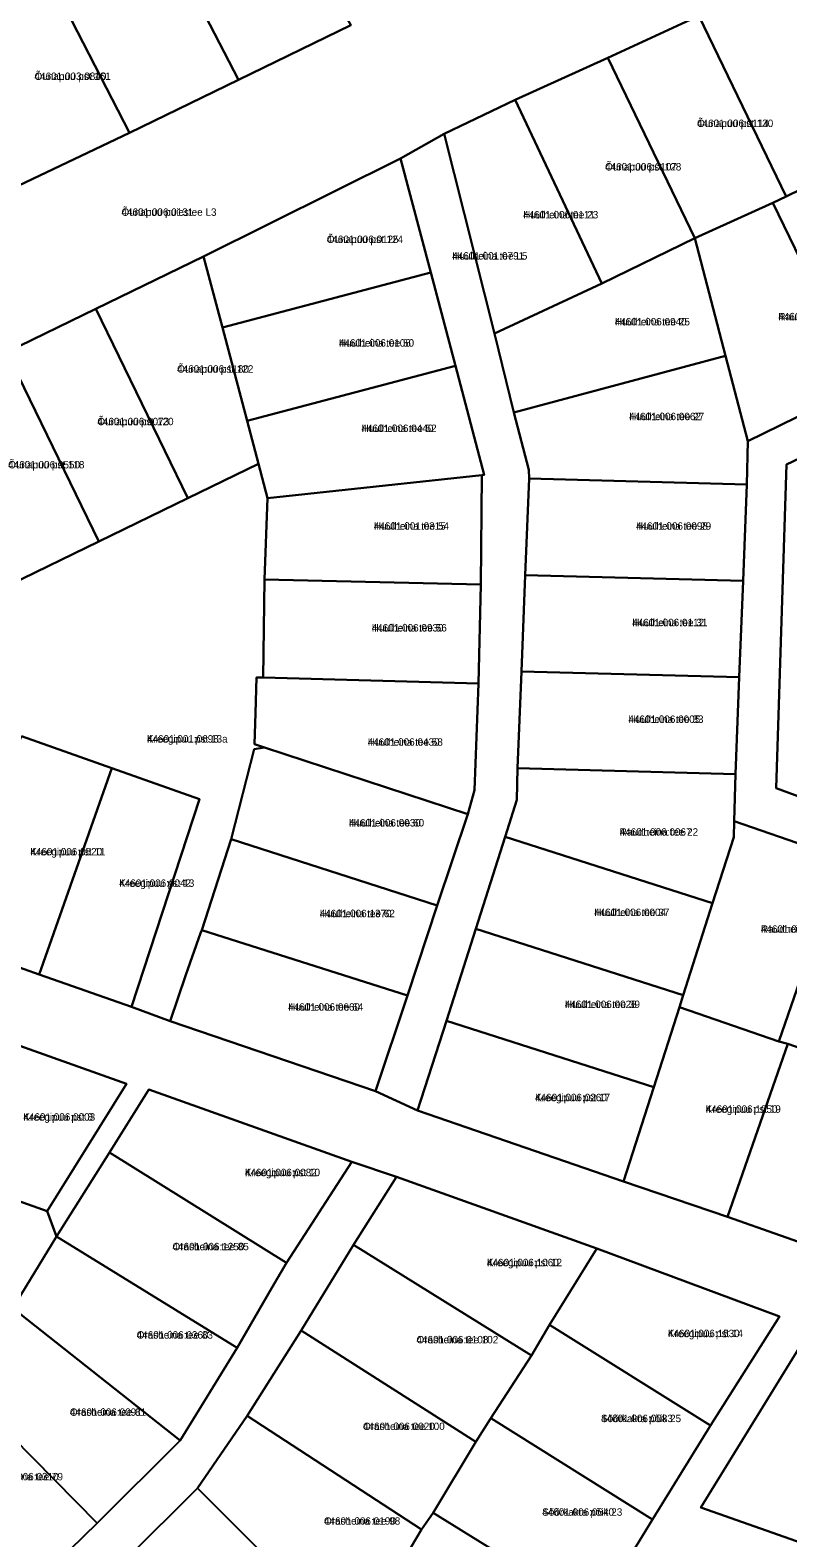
# Model space of a CAD drawing. Extents: x 551843 to 558501, y 6589003 to 6595718.
# Drawn here: x 553719.3 to 553872.3, y 6593051.3 to 6593355.7 of the extents above; entities that cross this region are included whole.
import ezdxf

# ---------------------------------------------------------------- set-up
doc = ezdxf.new("R2010")
doc.units = 0
for name, color, linetype in [('L_AADRESS', 7, 'Continuous'), ('PIIR', 7, 'Continuous'), ('TUNNUS', 7, 'Continuous')]:
    doc.layers.add(name, color=color, linetype=linetype)

msp = doc.modelspace()

# ---------------------------------------------------------------- linework, layer by layer
at = {"layer": 'PIIR'}
for points in [[(553755.85, 6593382.8), (553766.18, 6593387.81), (553784.07, 6593356.73), (553761.39, 6593345.7), (553744.97, 6593377.51)], [(553739.43, 6593335.04), (553723.03, 6593366.85), (553744.97, 6593377.51), (553761.39, 6593345.7)], [(553701.02, 6593356.45), (553717.5, 6593364.16), (553723.03, 6593366.85), (553739.43, 6593335.04), (553717.06, 6593324.38)], [(553854.3, 6593358.62), (553872.59, 6593367.51), (553890.23, 6593331.05), (553887.78, 6593329.87), (553871.99, 6593322.18)], [(553835.93, 6593350.16), (553854.3, 6593358.62), (553871.99, 6593322.18), (553869.25, 6593320.86), (553853.55, 6593313.74)], [(553817.25, 6593341.68), (553835.93, 6593350.16), (553853.55, 6593313.74), (553834.77, 6593304.59)], [(553802.94, 6593334.83), (553817.25, 6593341.68), (553834.77, 6593304.59), (553813.05, 6593294.48)], [(553810.52, 6593265.91), (553810.99, 6593265.94), (553805.21, 6593287.98), (553800.2, 6593306.84), (553794.13, 6593329.84), (553802.94, 6593334.83), (553813.05, 6593294.48), (553816.98, 6593278.53), (553820.03, 6593266.97), (553820.05, 6593265.2), (553819.28, 6593245.73), (553818.51, 6593226.23), (553817.74, 6593206.75), (553817.56, 6593200.35), (553815.24, 6593192.88), (553809.3, 6593174.31), (553803.37, 6593155.74), (553797.56, 6593137.62), (553789.06, 6593141.51), (553795.53, 6593160.86), (553801.53, 6593178.99), (553807.71, 6593197.46), (553809.04, 6593202.27), (553809.82, 6593223.82), (553810.32, 6593243.85)], [(553758.16, 6593295.7), (553754.37, 6593310.06), (553794.13, 6593329.84), (553800.2, 6593306.84)], [(553887.78, 6593329.87), (553905.73, 6593292.98), (553887.19, 6593283.97), (553869.25, 6593320.86), (553871.99, 6593322.18)], [(553869.25, 6593320.86), (553887.19, 6593283.97), (553864.2, 6593272.79), (553859.74, 6593289.98), (553853.55, 6593313.74)], [(553834.77, 6593304.59), (553853.55, 6593313.74), (553859.74, 6593289.98), (553816.98, 6593278.53), (553813.05, 6593294.48)], [(553732.62, 6593299.48), (553754.37, 6593310.06), (553758.16, 6593295.7), (553763.16, 6593276.85), (553765.42, 6593268.17), (553751.19, 6593261.25)], [(553758.16, 6593295.7), (553800.2, 6593306.84), (553805.21, 6593287.98), (553763.16, 6593276.85)], [(553714.63, 6593290.73), (553732.62, 6593299.48), (553751.19, 6593261.25), (553733.19, 6593252.5)], [(553696.64, 6593281.99), (553714.63, 6593290.73), (553733.19, 6593252.5), (553715.21, 6593243.76)], [(553859.74, 6593289.98), (553864.2, 6593272.79), (553864, 6593264.02), (553820.05, 6593265.2), (553820.03, 6593266.97), (553816.98, 6593278.53)], [(553765.42, 6593268.17), (553763.16, 6593276.85), (553805.21, 6593287.98), (553810.99, 6593265.94), (553810.52, 6593265.91), (553767.26, 6593261.24)], [(553898.78, 6593280.77), (553919.51, 6593228.18), (553925.34, 6593182.28), (553869.91, 6593202.68), (553872.03, 6593268.08)], [(553872.03, 6593268.08), (553869.91, 6593202.68), (553925.34, 6593182.28), (553919.51, 6593228.18), (553898.78, 6593280.77)], [(553810.32, 6593243.85), (553766.67, 6593244.84), (553767.26, 6593261.24), (553810.52, 6593265.91)], [(553819.28, 6593245.73), (553820.05, 6593265.2), (553864, 6593264.02), (553863.26, 6593244.57)], [(553766.67, 6593244.84), (553810.32, 6593243.85), (553809.82, 6593223.82), (553766.35, 6593225.03)], [(553819.28, 6593245.73), (553863.26, 6593244.57), (553862.49, 6593225.08), (553818.51, 6593226.23)], [(553765.01, 6593225.07), (553766.35, 6593225.03), (553809.82, 6593223.82), (553809.04, 6593202.27), (553807.71, 6593197.46), (553766.66, 6593210.92), (553764.66, 6593211.58), (553764.83, 6593217.86)], [(553818.51, 6593226.23), (553862.49, 6593225.08), (553861.72, 6593205.52), (553817.74, 6593206.75)], [(553717.61, 6593213.17), (553735.8, 6593206.72), (553721.14, 6593165.08), (553702.95, 6593171.53)], [(553801.53, 6593178.99), (553759.9, 6593192.43), (553764.54, 6593210.58), (553766.66, 6593210.92), (553807.71, 6593197.46)], [(553735.8, 6593206.72), (553753.5, 6593200.49), (553739.77, 6593158.52), (553721.14, 6593165.08)], [(553817.56, 6593200.35), (553817.74, 6593206.75), (553861.72, 6593205.52), (553861.46, 6593196.05), (553861.39, 6593192.79), (553857.12, 6593179.46), (553815.24, 6593192.88)], [(553851.18, 6593160.89), (553857.12, 6593179.46), (553861.39, 6593192.79), (553861.46, 6593196.05), (553883.28, 6593188.51), (553870.51, 6593151.58), (553850.43, 6593158.51)], [(553801.53, 6593178.99), (553795.53, 6593160.86), (553754, 6593174.03), (553759.9, 6593192.43)], [(553815.24, 6593192.88), (553857.12, 6593179.46), (553851.18, 6593160.89), (553809.3, 6593174.31)], [(553903.79, 6593181.43), (553890.99, 6593144.48), (553872.28, 6593151.07), (553870.51, 6593151.58), (553883.28, 6593188.51)], [(553789.06, 6593141.51), (553747.64, 6593155.65), (553750.76, 6593164.99), (553753.71, 6593173.45), (553754, 6593174.03), (553795.53, 6593160.86)], [(553851.18, 6593160.89), (553850.43, 6593158.51), (553845.25, 6593142.31), (553803.37, 6593155.74), (553809.3, 6593174.31)], [(553870.51, 6593151.58), (553872.28, 6593151.07), (553860.1, 6593116.14), (553839.15, 6593123.26), (553845.25, 6593142.31), (553850.43, 6593158.51)], [(553845.25, 6593142.31), (553839.15, 6593123.26), (553797.56, 6593137.62), (553803.37, 6593155.74)], [(553708.29, 6593153.86), (553738.79, 6593143.01), (553722.79, 6593117.28), (553698.37, 6593125.97)], [(553890.99, 6593144.48), (553893.7, 6593143.53), (553881.51, 6593108.6), (553860.1, 6593116.14), (553872.28, 6593151.07)], [(553735.35, 6593129.11), (553743.32, 6593141.86), (553784.29, 6593127.26), (553771.12, 6593106.86)], [(553667.82, 6593136.86), (553698.37, 6593125.97), (553722.79, 6593117.28), (553724.65, 6593112.16), (553715.84, 6593097.69), (553702.72, 6593084.85), (553688.9, 6593070.71), (553676.07, 6593057.76), (553659.09, 6593047.13), (553642.16, 6593036.49), (553629.16, 6593028.32), (553627.05, 6593033.11), (553664.19, 6593056.27), (553658.97, 6593070.69), (553652.27, 6593089.53), (553647.12, 6593103.99), (553648.53, 6593107.89), (553659.67, 6593124.55)], [(553643.89, 6592987.38), (553664.77, 6593000.5), (553681.43, 6593011.49), (553702.17, 6593024.66), (553719.27, 6593041.04), (553732.87, 6593054.27), (553749.62, 6593070.96), (553761.14, 6593089.7), (553768.13, 6593101.84), (553771.12, 6593106.86), (553784.29, 6593127.26), (553793.28, 6593124.2), (553784.6, 6593110.51), (553774.04, 6593093.19), (553763.13, 6593075.95), (553753.11, 6593061.38), (553738.72, 6593047.04), (553724.11, 6593032.4), (553709.85, 6593018.28), (553708.91, 6593017.72), (553696.33, 6593009.65), (553678.47, 6592998.33), (553659.91, 6592986.98), (553646.3, 6592978.3)], [(553724.65, 6593112.16), (553735.35, 6593129.11), (553771.12, 6593106.86), (553768.13, 6593101.84), (553761.14, 6593089.7)], [(553784.6, 6593110.51), (553793.28, 6593124.2), (553833.75, 6593109.74), (553824.18, 6593094.37), (553820.54, 6593088.16)], [(553715.84, 6593097.69), (553724.65, 6593112.16), (553761.14, 6593089.7), (553749.62, 6593070.96)], [(553784.6, 6593110.51), (553820.54, 6593088.16), (553812.37, 6593075.48), (553809.31, 6593070.71), (553774.04, 6593093.19)], [(553833.75, 6593109.74), (553870.59, 6593096.02), (553856.67, 6593073.99), (553824.18, 6593094.37)], [(553702.72, 6593084.85), (553715.84, 6593097.69), (553749.62, 6593070.96), (553732.87, 6593054.27)], [(553844.97, 6593055.03), (553812.37, 6593075.48), (553820.54, 6593088.16), (553824.18, 6593094.37), (553856.67, 6593073.99)], [(553854.75, 6593057.46), (553877.3, 6593094.1), (553895.01, 6593087.85), (553875.19, 6593050.25)], [(553763.13, 6593075.95), (553774.04, 6593093.19), (553809.31, 6593070.71), (553800.73, 6593056.39), (553798.33, 6593053.01)], [(553719.27, 6593041.04), (553688.9, 6593070.71), (553702.72, 6593084.85), (553732.87, 6593054.27)], [(553798.33, 6593053.01), (553789.9, 6593038.83), (553782.47, 6593032.03), (553753.11, 6593061.38), (553763.13, 6593075.95)], [(553800.73, 6593056.39), (553809.31, 6593070.71), (553812.37, 6593075.48), (553844.97, 6593055.03), (553833.4, 6593036.12)], [(553753.11, 6593061.38), (553782.47, 6593032.03), (553775.73, 6593024.7), (553768.31, 6593017.24), (553738.72, 6593047.04)], [(553789.9, 6593038.83), (553798.33, 6593053.01), (553800.73, 6593056.39), (553833.4, 6593036.12), (553820.22, 6593014.77)]]:
    msp.add_lwpolyline(points, close=True, dxfattribs=at)
for points in [[(553854.3, 6593358.62), (553835.93, 6593350.16), (553817.25, 6593341.68), (553802.94, 6593334.83), (553794.13, 6593329.84), (553754.37, 6593310.06), (553732.62, 6593299.48), (553714.63, 6593290.73)], [(553717.06, 6593324.38), (553739.43, 6593335.04), (553761.39, 6593345.7), (553784.07, 6593356.73)], [(553883.28, 6593188.51), (553861.46, 6593196.05), (553861.72, 6593205.52), (553862.49, 6593225.08), (553863.26, 6593244.57), (553864, 6593264.02), (553864.2, 6593272.79), (553887.19, 6593283.97)], [(553715.21, 6593243.76), (553733.19, 6593252.5), (553751.19, 6593261.25), (553765.42, 6593268.17), (553767.26, 6593261.24), (553766.67, 6593244.84), (553766.35, 6593225.03), (553765.01, 6593225.07), (553764.83, 6593217.86), (553764.66, 6593211.58), (553766.66, 6593210.92), (553764.54, 6593210.58), (553759.9, 6593192.43), (553754, 6593174.03), (553753.71, 6593173.45), (553750.76, 6593164.99), (553747.64, 6593155.65), (553739.77, 6593158.52), (553753.5, 6593200.49), (553735.8, 6593206.72), (553717.61, 6593213.17)], [(553702.95, 6593171.53), (553721.14, 6593165.08), (553739.77, 6593158.52), (553747.64, 6593155.65), (553789.06, 6593141.51), (553797.56, 6593137.62), (553839.15, 6593123.26), (553860.1, 6593116.14), (553881.51, 6593108.6), (553902.87, 6593101.36), (553924.28, 6593093.82), (553939.21, 6593088.15), (553965.62, 6593118.07), (553974.77, 6593128.95), (553993.24, 6593150.17), (554007.57, 6593145.12), (553973.99, 6593106.07), (553971.14, 6593106.63), (553953.7, 6593085.37), (553988.53, 6593074.47), (553988.44, 6593074.16), (554031.74, 6593060.29), (554035.59, 6593039.14)], [(553833.4, 6593036.12), (553844.97, 6593055.03), (553856.67, 6593073.99), (553870.59, 6593096.02), (553833.75, 6593109.74), (553793.28, 6593124.2), (553784.29, 6593127.26), (553743.32, 6593141.86), (553735.35, 6593129.11), (553724.65, 6593112.16), (553722.79, 6593117.28), (553738.79, 6593143.01), (553708.29, 6593153.86)], [(554031.39, 6593040.61), (553988.97, 6593055.28), (553958.82, 6593066), (553932.68, 6593074.58), (553913.88, 6593081.12), (553895.01, 6593087.85), (553877.3, 6593094.1), (553854.75, 6593057.46), (553875.19, 6593050.25)]]:
    msp.add_lwpolyline(points, dxfattribs=at)

# ---------------------------------------------------------------- texts
at = {"layer": 'L_AADRESS'}
for s, p in [('Õunapuu pst 161', (553720.23, 6593345.69)), ('Õunapuu pst 130', (553853.96, 6593336.19)), ('Õunapuu pst 128', (553835.4, 6593327.41)), ('Õunapuu puiestee L3', (553737.78, 6593318.26)), ('Huulheina tee 23', (553818.86, 6593317.73)), ('Õunapuu pst 124', (553779.23, 6593312.77)), ('Huulheina tee L5', (553804.55, 6593309.42)), ('Raudheina tee 12', (553870.37, 6593297.17)), ('Huulheina tee 25', (553837.37, 6593296.13)), ('Huulheina tee 50', (553781.68, 6593291.85)), ('Õunapuu pst 122', (553749.02, 6593286.59)), ('Õunapuu pst 120', (553732.91, 6593275.98)), ('Huulheina tee 27', (553840.25, 6593277)), ('Huulheina tee 52', (553786.23, 6593274.61)), ('Õunapuu pst 118', (553714.91, 6593267.26)), ('Huulheina tee 54', (553788.73, 6593254.88)), ('Huulheina tee 29', (553841.65, 6593254.88)), ('Huulheina tee 31', (553840.89, 6593235.4)), ('Huulheina tee 56', (553788.29, 6593234.33)), ('Huulheina tee 33', (553840.11, 6593215.88)), ('Kreegipuu pst 13a', (553742.92, 6593211.91)), ('Huulheina tee 58', (553787.49, 6593211.27)), ('Huulheina tee 60', (553783.71, 6593194.96)), ('Raudheina tee 22', (553838.35, 6593193.11)), ('Kreegipuu pst 11', (553719.38, 6593189.12)), ('Kreegipuu pst 13', (553737.32, 6593182.78)), ('Huulheina tee 62', (553777.8, 6593176.65)), ('Huulheina tee 37', (553833.21, 6593176.88)), ('Raudheina tee 24', (553866.86, 6593173.51)), ('Huulheina tee 64', (553771.42, 6593157.77)), ('Huulheina tee 39', (553827.28, 6593158.31)), ('Kreegipuu pst 17', (553821.26, 6593139.5)), ('Kreegipuu pst 8', (553717.97, 6593135.57)), ('Kreegipuu pst 19', (553855.71, 6593137.16)), ('Kreegipuu pst 10', (553762.7, 6593124.36)), ('Orasheina tee 85', (553748.08, 6593109.4)), ('Kreegipuu pst 12', (553811.55, 6593106.18)), ('Orasheina tee 83', (553740.85, 6593091.56)), ('Orasheina tee 102', (553797.34, 6593090.61)), ('Kreegipuu pst 14', (553848.07, 6593091.86)), ('Orasheina tee 81', (553727.37, 6593075.98)), ('Sõõrkakra põik 25', (553834.58, 6593074.7)), ('Orasheina tee 100', (553786.53, 6593073.1)), ('Orasheina tee 79', (553710.58, 6593062.95)), ('Sõõrkakra põik 23', (553822.71, 6593055.8)), ('Orasheina tee 98', (553778.66, 6593053.99))]:
    msp.add_text(s, height=1.5, dxfattribs=at).set_placement(p)
at = {"layer": 'TUNNUS'}
for s, p in [('44601:003:0840', (553720.23, 6593345.69)), ('44601:006:0114', (553853.96, 6593336.19)), ('44601:006:0107', (553835.4, 6593327.41)), ('44601:006:0131', (553737.78, 6593318.26)), ('44601:006:0111', (553818.86, 6593317.73)), ('44601:006:0125', (553779.23, 6593312.77)), ('44601:001:0791', (553804.55, 6593309.42)), ('44601:006:0990', (553870.37, 6593297.17)), ('44601:006:0940', (553837.37, 6593296.13)), ('44601:006:0106', (553781.68, 6593291.85)), ('44601:006:1180', (553749.02, 6593286.59)), ('44601:006:0073', (553732.91, 6593275.98)), ('44601:006:0062', (553840.25, 6593277)), ('44601:006:0440', (553786.23, 6593274.61)), ('44601:006:0550', (553714.91, 6593267.26)), ('44601:001:0315', (553788.73, 6593254.88)), ('44601:006:0098', (553841.65, 6593254.88)), ('44601:006:0112', (553840.89, 6593235.4)), ('44601:006:0930', (553788.29, 6593234.33)), ('44601:006:0005', (553840.11, 6593215.88)), ('44601:001:0698', (553742.92, 6593211.91)), ('44601:006:0430', (553787.49, 6593211.27)), ('44601:006:0030', (553783.71, 6593194.96)), ('44601:006:0067', (553838.35, 6593193.11)), ('44601:006:0520', (553719.38, 6593189.12)), ('44601:006:0042', (553737.32, 6593182.78)), ('44601:006:1370', (553777.8, 6593176.65)), ('44601:006:0004', (553833.21, 6593176.88)), ('44601:006:0008', (553866.86, 6593173.51)), ('44601:006:0660', (553771.42, 6593157.77)), ('44601:006:0028', (553827.28, 6593158.31)), ('44601:006:0260', (553821.26, 6593139.5)), ('44601:006:0003', (553717.97, 6593135.57)), ('44601:006:1050', (553855.71, 6593137.16)), ('44601:006:0082', (553762.7, 6593124.36)), ('44601:006:1250', (553748.08, 6593109.4)), ('44601:006:1060', (553811.55, 6593106.18)), ('44601:006:0360', (553740.85, 6593091.56)), ('44601:006:0108', (553797.34, 6593090.61)), ('44601:006:1530', (553848.07, 6593091.86)), ('44601:006:0091', (553727.37, 6593075.98)), ('44601:006:0083', (553834.58, 6593074.7)), ('44601:006:0020', (553786.53, 6593073.1)), ('44601:006:0310', (553710.58, 6593062.95)), ('44601:006:0640', (553822.71, 6593055.8)), ('44601:006:0190', (553778.66, 6593053.99))]:
    msp.add_text(s, height=1.5, dxfattribs=at).set_placement(p)

doc.saveas('drawing.dxf')
